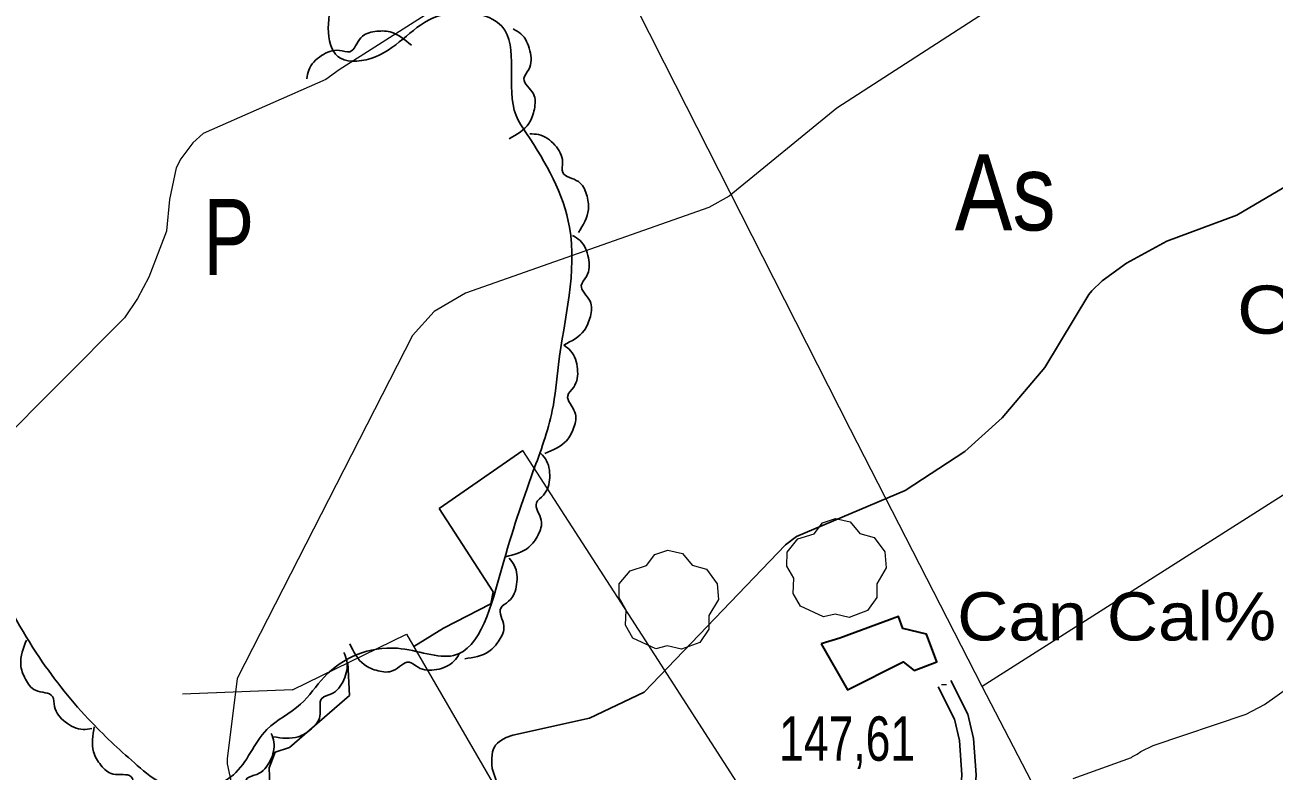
# Model space of a CAD drawing. Extents: x 483847 to 488453, y 4383581 to 4386795.
# Drawn here: x 484722.9 to 484969.3, y 4384859.8 to 4385007 of the extents above; entities that cross this region are included whole.
import ezdxf
from ezdxf.enums import TextEntityAlignment as Align

# ---------------------------------------------------------------- set-up
doc = ezdxf.new("R2010")
doc.units = 0
doc.header["$LTSCALE"] = 3.8
doc.linetypes.add('LONG_DASHED', pattern=[7.5, 6, -1.5])
doc.linetypes.add('MEDIUM_DASHED', pattern=[4.5, 3, -1.5])
for name, color, linetype, lineweight in [('25', 7, 'LONG_DASHED', 25), ('27', 7, 'Continuous', 25), ('29', 7, 'Continuous', 13), ('38', 7, 'Continuous', 25), ('47', 7, 'Continuous', 35), ('51', 7, 'Continuous', 13), ('7', 7, 'Continuous', 13), ('8', 7, 'Continuous', 25), ('9', 7, 'Continuous', 13)]:
    doc.layers.add(name, color=color, linetype=linetype, lineweight=lineweight)
doc.layers.add('31', color=7, linetype='Continuous')
doc.layers.add('5', color=7, linetype='Continuous')

msp = doc.modelspace()

# ---------------------------------------------------------------- linework, layer by layer
at = {"layer": '25'}
for points in [[(484799.57, 4384884.38), (484805.47, 4384888.01), (484814.81, 4384892.78), (484815.24, 4384895.2), (484804.63, 4384911.64), (484821.07, 4384923.08)], [(484786.56, 4384881.18), (484786.93, 4384874.73), (484775.08, 4384864.47), (484772.28, 4384863.57), (484771.09, 4384860.45), (484771.24, 4384855.33), (484772.14, 4384851.64), (484772.28, 4384847.07)]]:
    msp.add_lwpolyline(points, dxfattribs=at)
at = {"layer": '27'}
for points in [[(484700.82, 4384968.46), (484705.41, 4384959.43), (484707.55, 4384953.09), (484707.74, 4384939), (484711.22, 4384919.64), (484712.92, 4384912.69), (484716.8, 4384899.3), (484725.74, 4384882.24), (484736.07, 4384869.4), (484745.06, 4384860.93), (484750.28, 4384857.29), (484764, 4384859.06), (484770.61, 4384868.01), (484777.26, 4384873.01), (484781.91, 4384878.36), (484796.36, 4384884.03), (484807.44, 4384882.61), (484816.96, 4384899.83), (484823.17, 4384919.01), (484826.91, 4384930.91), (484828.12, 4384939.98), (484830.31, 4384967.09), (484821.85, 4384985.57), (484819.78, 4384989.11), (484816.96, 4385006.72), (484804.17, 4385008.65), (484792.01, 4385000.71), (484785.16, 4385000.41), (484783.76, 4385012.32), (484786.61, 4385017.19), (484802.93, 4385029.89), (484816.99, 4385036.63), (484831.62, 4385042.77), (484831.85, 4385052.42), (484828.77, 4385053.4), (484819, 4385062.66), (484818.83, 4385065.3), (484812.25, 4385067.05), (484801.05, 4385062.91), (484791.28, 4385056.88), (484772.36, 4385043.62), (484767.88, 4385041.12), (484748.05, 4385041.41), (484745.09, 4385048.67), (484744.52, 4385049.12), (484744.55, 4385052.7), (484748.79, 4385058.77), (484748.64, 4385063.3), (484740.19, 4385063.82), (484742.63, 4385070.57), (484763.21, 4385085.99), (484768.65, 4385092.72), (484762.05, 4385095.21), (484749.87, 4385090.39), (484739.63, 4385082.24), (484731.52, 4385075.98), (484695.06, 4385038.96)], [(484778.48, 4384996.36), (484778.87, 4384998.09), (484781.37, 4385000.93), (484784.92, 4385001.96), (484786.96, 4385001.7), (484789.17, 4385004.48), (484791.91, 4385005.68), (484794.93, 4385005.62), (484799.14, 4385002.99)], [(484819.2, 4385006.19), (484820.69, 4385005.24), (484822.51, 4385001.91), (484822.26, 4384998.22), (484821.33, 4384996.4), (484823.18, 4384993.37), (484823.37, 4384990.39), (484822.29, 4384987.56), (484818.38, 4384984.51)], [(484822.45, 4384985.48), (484824.22, 4384985.36), (484827.41, 4384983.29), (484828.94, 4384979.94), (484828.99, 4384977.88), (484832.06, 4384976.1), (484833.65, 4384973.57), (484834.04, 4384970.57), (484832.06, 4384966.03)], [(484830.92, 4384965.48), (484832.38, 4384964.46), (484834.05, 4384961.06), (484833.65, 4384957.39), (484832.63, 4384955.61), (484834.36, 4384952.5), (484834.42, 4384949.51), (484833.22, 4384946.74), (484829.18, 4384943.85)], [(484829.17, 4384943.85), (484830.52, 4384942.7), (484831.87, 4384939.15), (484831.13, 4384935.54), (484829.95, 4384933.86), (484831.38, 4384930.6), (484831.17, 4384927.62), (484829.71, 4384924.97), (484825.43, 4384922.47)], [(484824.37, 4384922.74), (484825.55, 4384921.41), (484826.4, 4384917.72), (484825.16, 4384914.24), (484823.77, 4384912.73), (484824.73, 4384909.31), (484824.11, 4384906.39), (484822.3, 4384903.97), (484817.71, 4384902.09)], [(484818.38, 4384901.84), (484819.41, 4384900.4), (484819.88, 4384896.64), (484818.29, 4384893.3), (484816.75, 4384891.95), (484817.36, 4384888.45), (484816.44, 4384885.61), (484814.39, 4384883.38), (484809.63, 4384881.98)], [(484736.12, 4384868.22), (484734.36, 4384868.04), (484730.86, 4384869.5), (484728.75, 4384872.53), (484728.34, 4384874.55), (484725, 4384875.75), (484722.99, 4384877.96), (484722.07, 4384880.84), (484723.21, 4384885.67)], [(484808.56, 4384882.92), (484807.52, 4384881.48), (484804.1, 4384879.84), (484800.44, 4384880.29), (484798.66, 4384881.32), (484795.54, 4384879.63), (484792.55, 4384879.6), (484789.79, 4384880.83), (484786.95, 4384884.9)], [(484785.78, 4384883.21), (484786.38, 4384881.54), (484785.78, 4384877.8), (484783.33, 4384875.03), (484781.47, 4384874.16), (484781.08, 4384870.63), (484779.41, 4384868.16), (484776.82, 4384866.59), (484771.86, 4384866.56)], [(484752.71, 4384854.05), (484751.01, 4384853.52), (484747.29, 4384854.26), (484744.62, 4384856.8), (484743.82, 4384858.7), (484740.3, 4384859.21), (484737.89, 4384860.97), (484736.42, 4384863.61), (484736.58, 4384868.57)], [(484771.49, 4384867.23), (484772.01, 4384865.53), (484771.24, 4384861.82), (484768.66, 4384859.17), (484766.76, 4384858.39), (484766.22, 4384854.88), (484764.43, 4384852.49), (484761.77, 4384851.04), (484756.82, 4384851.24)]]:
    msp.add_spline(points, degree=3, dxfattribs=at)
at = {"layer": '29'}
for points in [[(484880.39, 4384890.21), (484875.85, 4384892.33), (484874.44, 4384894.87), (484874.54, 4384897.85), (484873.17, 4384900.26), (484873.21, 4384903.01), (484875.37, 4384905.61), (484878.56, 4384906.61), (484880.21, 4384908.8), (484882.78, 4384909.63), (484885.64, 4384908.98), (484887.59, 4384906.71), (484890.4, 4384905.89), (484892.53, 4384903.04), (484892.77, 4384899.91), (484890.89, 4384896.76), (484890.89, 4384894.08), (484889.07, 4384891.47), (484885.45, 4384890.13), (484882.68, 4384890.76)], [(484847.31, 4384883.94), (484842.77, 4384886.06), (484841.36, 4384888.6), (484841.46, 4384891.58), (484840.09, 4384893.99), (484840.13, 4384896.74), (484842.29, 4384899.34), (484845.48, 4384900.34), (484847.13, 4384902.53), (484849.7, 4384903.36), (484852.56, 4384902.71), (484854.51, 4384900.44), (484857.32, 4384899.62), (484859.45, 4384896.77), (484859.69, 4384893.64), (484857.81, 4384890.49), (484857.81, 4384887.81), (484855.99, 4384885.2), (484852.37, 4384883.86), (484849.6, 4384884.49)]]:
    msp.add_lwpolyline(points, close=True, dxfattribs=at)
at = {"layer": '38'}
msp.add_lwpolyline([(484903.02, 4384876.44), (484906.24, 4384870.08), (484907.21, 4384865.83), (484907.69, 4384859.08), (484907.25, 4384851.84), (484907.86, 4384842.23), (484910.97, 4384832.52), (484914.43, 4384826.25), (484918.03, 4384821.21), (484920.72, 4384818.22), (484924.11, 4384812.75), (484926.24, 4384807.29), (484927.2, 4384801.62), (484927.85, 4384798.98), (484930.72, 4384793.77), (484933.02, 4384789.62)], dxfattribs=at)
at = {"layer": '38', "linetype": 'MEDIUM_DASHED'}
msp.add_lwpolyline([(484905.53, 4384877.71), (484908.9, 4384871.04), (484910, 4384866.25), (484910.51, 4384859.1), (484910.07, 4384851.84), (484910.65, 4384842.75), (484913.57, 4384833.64), (484916.81, 4384827.75), (484920.23, 4384822.97), (484922.97, 4384819.91), (484926.63, 4384814.02), (484928.96, 4384808.04), (484929.96, 4384802.19), (484930.49, 4384800.01), (484933.16, 4384795.18), (484935.87, 4384791.16)], dxfattribs=at)
at = {"layer": '47'}
msp.add_lwpolyline([(484879.93, 4384884.92), (484885.11, 4384875.86), (484896.1, 4384881.38), (484898.26, 4384879.63), (484902.78, 4384881.34), (484900.72, 4384886.83), (484896.05, 4384887.95), (484895.21, 4384890.28), (484883.65, 4384886.02)], close=True, dxfattribs=at)
at = {"layer": '51'}
for p, q in [((484951.4, 4384800.3), (484911.71, 4384876.49)), ((484775.66, 4384875.87), (484753.95, 4384874.99))]:
    msp.add_line(p, q, dxfattribs=at)
for points in [[(485328.87, 4385195.8), (485265.59, 4385143.47), (485157.32, 4385054.04), (485059.13, 4384970.21), (484911.71, 4384876.49), (484885.71, 4384927.18), (484849.05, 4384999.44), (484792.69, 4385110.93), (484799.92, 4385117.05), (484828.88, 4385118.96)], [(484911.41, 4384779.29), (484879.46, 4384832.49), (484844.66, 4384886.65), (484821.07, 4384923.08)], [(484775.66, 4384875.87), (484798.15, 4384886.83), (484835.73, 4384821.98), (484874.95, 4384759.41)]]:
    msp.add_lwpolyline(points, dxfattribs=at)
at = {"layer": '7'}
msp.add_line((484903.66, 4384876.92), (484904.66, 4384876.92), dxfattribs=at)
at = {"layer": '8'}
msp.add_lwpolyline([(484817.75, 4384852.28), (484815.06, 4384860.31), (484814.98, 4384861.04), (484814.98, 4384862.36), (484815.13, 4384863.6), (484815.32, 4384864.19), (484815.56, 4384864.66), (484815.73, 4384864.9), (484816.08, 4384865.31), (484816.48, 4384865.66), (484817.23, 4384866.14), (484817.84, 4384866.42), (484819.13, 4384866.87), (484834.28, 4384870.24), (484845, 4384875.35), (484872.9, 4384904.47), (484875.05, 4384906.09), (484896.5, 4384915.14), (484908.28, 4384922.83), (484915.63, 4384929.46), (484924.06, 4384939.44), (484932.75, 4384953.81), (484933.35, 4384954.53), (484935.35, 4384956.49), (484940.16, 4384960.03), (484948.14, 4384964.32), (484961.92, 4384969.47), (485056.77, 4385025.37)], dxfattribs=at)
at = {"layer": '9'}
for points in [[(485012.73, 4385113.3), (484889.47, 4385050.96), (484820.78, 4385021.02), (484784.87, 4384998.15), (484782.22, 4384996.23), (484758.08, 4384985.58), (484756.02, 4384983.76), (484753.62, 4384980.6), (484752.71, 4384978.83), (484751.41, 4384972.59), (484750.82, 4384966.4), (484750.8, 4384966.36), (484750.8, 4384966.35), (484750.8, 4384966.34), (484747.34, 4384957.24), (484745.13, 4384953.01)], [(485032.2, 4385066.42), (484940.16, 4385027.51), (484883.04, 4384990.57), (484861.78, 4384973.2), (484857.81, 4384970.95), (484809.81, 4384954.08), (484803.64, 4384950.46), (484799.36, 4384945.72), (484764.77, 4384878.08), (484762.76, 4384862.2), (484762.78, 4384861.26), (484763.85, 4384856.41)], [(484745.13, 4384953.01), (484742.52, 4384949.21), (484717.09, 4384923.73), (484707.54, 4384910.25), (484681.81, 4384867.19), (484666.9, 4384847.65)], [(484929.67, 4384858.38), (484941.12, 4384862.52), (484941.26, 4384862.65), (484941.32, 4384862.69), (484942.24, 4384863.17), (484942.99, 4384863.66), (484945.43, 4384864.88), (484963.74, 4384871.01), (484967.4, 4384872.92), (485009.83, 4384903.13), (485014.51, 4384907.63)]]:
    msp.add_lwpolyline(points, dxfattribs=at)

# ---------------------------------------------------------------- texts
at = {"layer": '31'}
for s, width, p in [('As', 0.85, (484916.24, 4384966.46)), ('P', 0.75, (484763.1, 4384957.67))]:
    msp.add_text(s, height=15, dxfattribs=dict(at, width=width)).set_placement(p, align=Align.CENTER)
at = {"layer": '5', "width": 1.2}
msp.add_text('Can Jaqueta', height=9.5, dxfattribs=at).set_placement((485048.39, 4384946.09), align=Align.RIGHT)
at = {"layer": '5', "width": 1.1}
msp.add_text('Can Cal%', height=9.5, dxfattribs=at).set_placement((484906.77, 4384885.58))
at = {"layer": '7', "width": 0.75}
msp.add_text('147,61', height=8.75, dxfattribs=at).set_placement((484871.64, 4384861.85))

doc.saveas('drawing.dxf')
